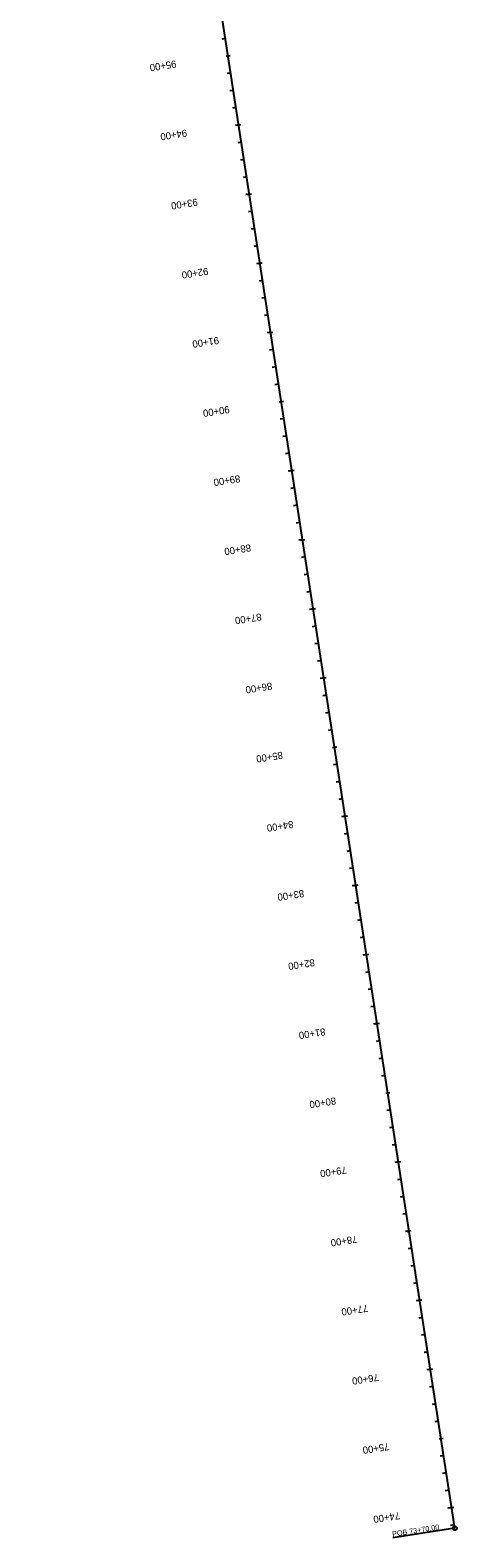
# Model space of a CAD drawing. Extents: x 11526485 to 11527255, y 9590594 to 9599170.
# Drawn here: x 11526645 to 11527255, y 9590594 to 9592749 of the extents above; entities that cross this region are included whole.
import ezdxf

# ---------------------------------------------------------------- set-up
doc = ezdxf.new("R2010")
doc.units = 0
for name, color, linetype in [('Alignment', 7, 'Continuous'), ('Default', 7, 'Continuous'), ('TextAlignment', 7, 'Continuous'), ('TextAlignmentLrg', 7, 'Continuous'), ('TextAlignmentSml', 7, 'Continuous')]:
    doc.layers.add(name, color=color, linetype=linetype)

msp = doc.modelspace()

# ---------------------------------------------------------------- linework, layer by layer
at = {"layer": 'Alignment'}
msp.add_line((11527252.3, 9590607.6), (11526645, 9594551), dxfattribs=at)
at = {"layer": 'Default'}
msp.add_line((11527252.3, 9590607.6), (11526645, 9594551), dxfattribs=at)
at = {"layer": 'TextAlignment'}
for p in [(11527252.3, 9590607.6), (11527163.3, 9590593.9)]:
    msp.add_line(p, (11527163.3, 9590593.9), dxfattribs=at)
msp.add_circle((11527252.3, 9590607.6), 2.67, dxfattribs=at)
at = {"layer": 'TextAlignmentLrg'}
for p, q in [((11526925.1, 9592712.3), (11526931.1, 9592713.3)), ((11526943.3, 9592614), (11526937.9, 9592613.1)), ((11526958.6, 9592515.1), (11526953.2, 9592514.3)), ((11526973.8, 9592416.3), (11526968.4, 9592415.5)), ((11526989, 9592317.5), (11526983.6, 9592316.6)), ((11527001.2, 9592218.2), (11527007.2, 9592219.1)), ((11527019.4, 9592119.8), (11527014, 9592119)), ((11527034.7, 9592021), (11527029.3, 9592020.1)), ((11527049.9, 9591922.1), (11527044.5, 9591921.3)), ((11527065.1, 9591823.3), (11527059.7, 9591822.5)), ((11527077.3, 9591724), (11527083.3, 9591724.9)), ((11527095.5, 9591625.6), (11527090.1, 9591624.8)), ((11527110.8, 9591526.8), (11527105.4, 9591526)), ((11527126, 9591428), (11527120.6, 9591427.1)), ((11527141.2, 9591329.1), (11527135.8, 9591328.3)), ((11527153.4, 9591229.8), (11527159.4, 9591230.7)), ((11527171.6, 9591131.4), (11527166.2, 9591130.6)), ((11527186.9, 9591032.6), (11527181.5, 9591031.8)), ((11527202.1, 9590933.8), (11527196.7, 9590932.9)), ((11527217.3, 9590834.9), (11527211.9, 9590834.1)), ((11527229.5, 9590735.6), (11527235.5, 9590736.6)), ((11527247.7, 9590637.3), (11527242.3, 9590636.4))]:
    msp.add_line(p, q, dxfattribs=at)
at = {"layer": 'TextAlignmentSml'}
for p, q in [((11526924.3, 9592737.5), (11526918.9, 9592736.7)), ((11526925.1, 9592712.3), (11526931.1, 9592713.3)), ((11526931.9, 9592688.1), (11526926.5, 9592687.3)), ((11526935.7, 9592663.4), (11526930.3, 9592662.6)), ((11526939.5, 9592638.7), (11526934.1, 9592637.8)), ((11526940.3, 9592613.5), (11526946.4, 9592614.4)), ((11526947.1, 9592589.3), (11526941.7, 9592588.4)), ((11526950.9, 9592564.6), (11526945.5, 9592563.7)), ((11526954.8, 9592539.8), (11526949.4, 9592539)), ((11526955.5, 9592514.7), (11526961.6, 9592515.6)), ((11526962.4, 9592490.4), (11526957, 9592489.6)), ((11526966.2, 9592465.7), (11526960.8, 9592464.9)), ((11526970, 9592441), (11526964.6, 9592440.2)), ((11526970.8, 9592415.8), (11526976.8, 9592416.8)), ((11526977.6, 9592391.6), (11526972.2, 9592390.8)), ((11526981.4, 9592366.9), (11526976, 9592366.1)), ((11526985.2, 9592342.2), (11526979.8, 9592341.3)), ((11526986, 9592317), (11526992, 9592317.9)), ((11526992.8, 9592292.8), (11526987.4, 9592291.9)), ((11526996.6, 9592268), (11526991.2, 9592267.2)), ((11527000.4, 9592243.3), (11526995, 9592242.5)), ((11527001.2, 9592218.2), (11527007.2, 9592219.1)), ((11527008, 9592193.9), (11527002.6, 9592193.1)), ((11527011.8, 9592169.2), (11527006.4, 9592168.4)), ((11527015.6, 9592144.5), (11527010.2, 9592143.7)), ((11527016.4, 9592119.3), (11527022.5, 9592120.3)), ((11527023.2, 9592095.1), (11527017.8, 9592094.3)), ((11527027, 9592070.4), (11527021.6, 9592069.5)), ((11527030.8, 9592045.7), (11527025.5, 9592044.8)), ((11527031.6, 9592020.5), (11527037.7, 9592021.4)), ((11527038.5, 9591996.3), (11527033.1, 9591995.4)), ((11527042.3, 9591971.5), (11527036.9, 9591970.7)), ((11527046.1, 9591946.8), (11527040.7, 9591946)), ((11527046.8, 9591921.7), (11527052.9, 9591922.6)), ((11527053.7, 9591897.4), (11527048.3, 9591896.6)), ((11527057.5, 9591872.7), (11527052.1, 9591871.9)), ((11527061.3, 9591848), (11527055.9, 9591847.2)), ((11527062.1, 9591822.8), (11527068.1, 9591823.8)), ((11527068.9, 9591798.6), (11527063.5, 9591797.8)), ((11527072.7, 9591773.9), (11527067.3, 9591773)), ((11527076.5, 9591749.2), (11527071.1, 9591748.3)), ((11527077.3, 9591724), (11527083.3, 9591724.9)), ((11527084.1, 9591699.7), (11527078.7, 9591698.9)), ((11527087.9, 9591675), (11527082.5, 9591674.2)), ((11527091.7, 9591650.3), (11527086.3, 9591649.5)), ((11527092.5, 9591625.2), (11527098.6, 9591626.1)), ((11527099.3, 9591600.9), (11527093.9, 9591600.1)), ((11527103.1, 9591576.2), (11527097.7, 9591575.4)), ((11527106.9, 9591551.5), (11527101.6, 9591550.7)), ((11527107.7, 9591526.3), (11527113.8, 9591527.3)), ((11527114.6, 9591502.1), (11527109.2, 9591501.2)), ((11527118.4, 9591477.4), (11527113, 9591476.5)), ((11527122.2, 9591452.7), (11527116.8, 9591451.8)), ((11527122.9, 9591427.5), (11527129, 9591428.4)), ((11527129.8, 9591403.2), (11527124.4, 9591402.4)), ((11527133.6, 9591378.5), (11527128.2, 9591377.7)), ((11527137.4, 9591353.8), (11527132, 9591353)), ((11527138.2, 9591328.7), (11527144.2, 9591329.6)), ((11527145, 9591304.4), (11527139.6, 9591303.6)), ((11527148.8, 9591279.7), (11527143.4, 9591278.9)), ((11527152.6, 9591255), (11527147.2, 9591254.2)), ((11527153.4, 9591229.8), (11527159.4, 9591230.7)), ((11527160.2, 9591205.6), (11527154.8, 9591204.7)), ((11527164, 9591180.9), (11527158.6, 9591180)), ((11527167.8, 9591156.2), (11527162.4, 9591155.3)), ((11527168.6, 9591131), (11527174.7, 9591131.9)), ((11527175.4, 9591106.7), (11527170, 9591105.9)), ((11527179.2, 9591082), (11527173.8, 9591081.2)), ((11527183, 9591057.3), (11527177.6, 9591056.5)), ((11527183.8, 9591032.1), (11527189.9, 9591033.1)), ((11527190.7, 9591007.9), (11527185.3, 9591007.1)), ((11527194.5, 9590983.2), (11527189.1, 9590982.4)), ((11527198.3, 9590958.5), (11527192.9, 9590957.7)), ((11527199, 9590933.3), (11527205.1, 9590934.2)), ((11527205.9, 9590909.1), (11527200.5, 9590908.2)), ((11527209.7, 9590884.4), (11527204.3, 9590883.5)), ((11527213.5, 9590859.6), (11527208.1, 9590858.8)), ((11527214.3, 9590834.5), (11527220.3, 9590835.4)), ((11527221.1, 9590810.2), (11527215.7, 9590809.4)), ((11527224.9, 9590785.5), (11527219.5, 9590784.7)), ((11527228.7, 9590760.8), (11527223.3, 9590760)), ((11527229.5, 9590735.6), (11527235.5, 9590736.6)), ((11527236.3, 9590711.4), (11527230.9, 9590710.6)), ((11527240.1, 9590686.7), (11527234.7, 9590685.9)), ((11527243.9, 9590662), (11527238.5, 9590661.1)), ((11527244.7, 9590636.8), (11527250.8, 9590637.7)), ((11527251.5, 9590612.6), (11527246.1, 9590611.7))]:
    msp.add_line(p, q, dxfattribs=at)

# ---------------------------------------------------------------- texts
at = {"layer": 'TextAlignment'}
for s, p in [('POB ', (11527163.1, 9590595.5)), ('73+70.00', (11527187.4, 9590599.3))]:
    msp.add_text(s, height=7.5, rotation=8.7543, dxfattribs=at).set_placement(p)
at = {"layer": 'TextAlignmentLrg'}
for s, p in [('95+00', (11526853.2, 9592706.4)), ('90+00', (11526929.3, 9592212.3)), ('85+00', (11527005.4, 9591718.1)), ('80+00', (11527081.5, 9591223.9)), ('75+00', (11527157.6, 9590729.7))]:
    msp.add_text(s, height=10.2, rotation=188.7543, dxfattribs=at).set_placement(p)
at = {"layer": 'TextAlignmentSml'}
for s, p in [('95+00', (11526853.2, 9592706.4)), ('94+00', (11526868.4, 9592607.6)), ('93+00', (11526883.7, 9592508.8)), ('92+00', (11526898.9, 9592409.9)), ('91+00', (11526914.1, 9592311.1)), ('90+00', (11526929.3, 9592212.3)), ('89+00', (11526944.5, 9592113.4)), ('88+00', (11526959.8, 9592014.6)), ('87+00', (11526975, 9591915.8)), ('86+00', (11526990.2, 9591816.9)), ('85+00', (11527005.4, 9591718.1)), ('84+00', (11527020.6, 9591619.2)), ('83+00', (11527035.8, 9591520.4)), ('82+00', (11527051.1, 9591421.6)), ('81+00', (11527066.3, 9591322.7)), ('80+00', (11527081.5, 9591223.9)), ('79+00', (11527096.7, 9591125.1)), ('78+00', (11527111.9, 9591026.2)), ('77+00', (11527127.2, 9590927.4)), ('76+00', (11527142.4, 9590828.6)), ('75+00', (11527157.6, 9590729.7)), ('74+00', (11527172.8, 9590630.9))]:
    msp.add_text(s, height=10.2, rotation=188.7543, dxfattribs=at).set_placement(p)

doc.saveas('drawing.dxf')
